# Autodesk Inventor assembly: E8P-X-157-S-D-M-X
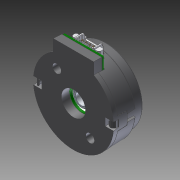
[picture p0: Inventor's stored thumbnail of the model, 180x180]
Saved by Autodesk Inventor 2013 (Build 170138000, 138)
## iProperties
Created: 2012-07
Part Number: E8P-X-157-S-D-M-X
Document SubType Name: Assembly
Designer: rYan
Mass: 3.85599 g
Surface Area: 74.5599 cm^2
Volume: 3.85599 cm^3
Density: 1 g/cm^3
Author: rYan
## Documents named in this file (8)
- D:\SVN\2013\Inventor\Kaufteile\E8P-X-157-S-D-M-X\E8P-X-157-S-D-M-X.iam
- D:\SVN\2013\Inventor\Kaufteile\E8P-X-157-S-D-M-X\E8P-X-157-S-D-M-X.ipt
- D:\SVN\2013\Inventor\Kaufteile\E8P-X-157-S-D-M-X\E8P-X-157-S-D-M-X_1.ipt
- D:\SVN\2013\Inventor\Kaufteile\E8P-X-157-S-D-M-X\E8P-X-157-S-D-M-X_2.ipt
- D:\SVN\2013\Inventor\Kaufteile\E8P-X-157-S-D-M-X\E8P-X-157-S-D-M-X_3.ipt
- D:\SVN\2013\Inventor\Kaufteile\E8P-X-157-S-D-M-X\E8P-X-157-S-D-M-X_4.ipt
- D:\SVN\2013\Inventor\Kaufteile\E8P-X-157-S-D-M-X\E8P-X-157-S-D-M-X_5.ipt
- D:\SVN\2013\Inventor\Kaufteile\E8P-X-157-S-D-M-X\E8P-X-157-S-D-M-X_6.ipt
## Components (7 placed, 7 different names)
1. E8P-X-157-S-D-M-X:1
2. E8P-X-157-S-D-M-X_1:1
3. E8P-X-157-S-D-M-X_2:1
4. E8P-X-157-S-D-M-X_3:1
5. E8P-X-157-S-D-M-X_4:1
6. E8P-X-157-S-D-M-X_5:1
7. E8P-X-157-S-D-M-X_6:1
